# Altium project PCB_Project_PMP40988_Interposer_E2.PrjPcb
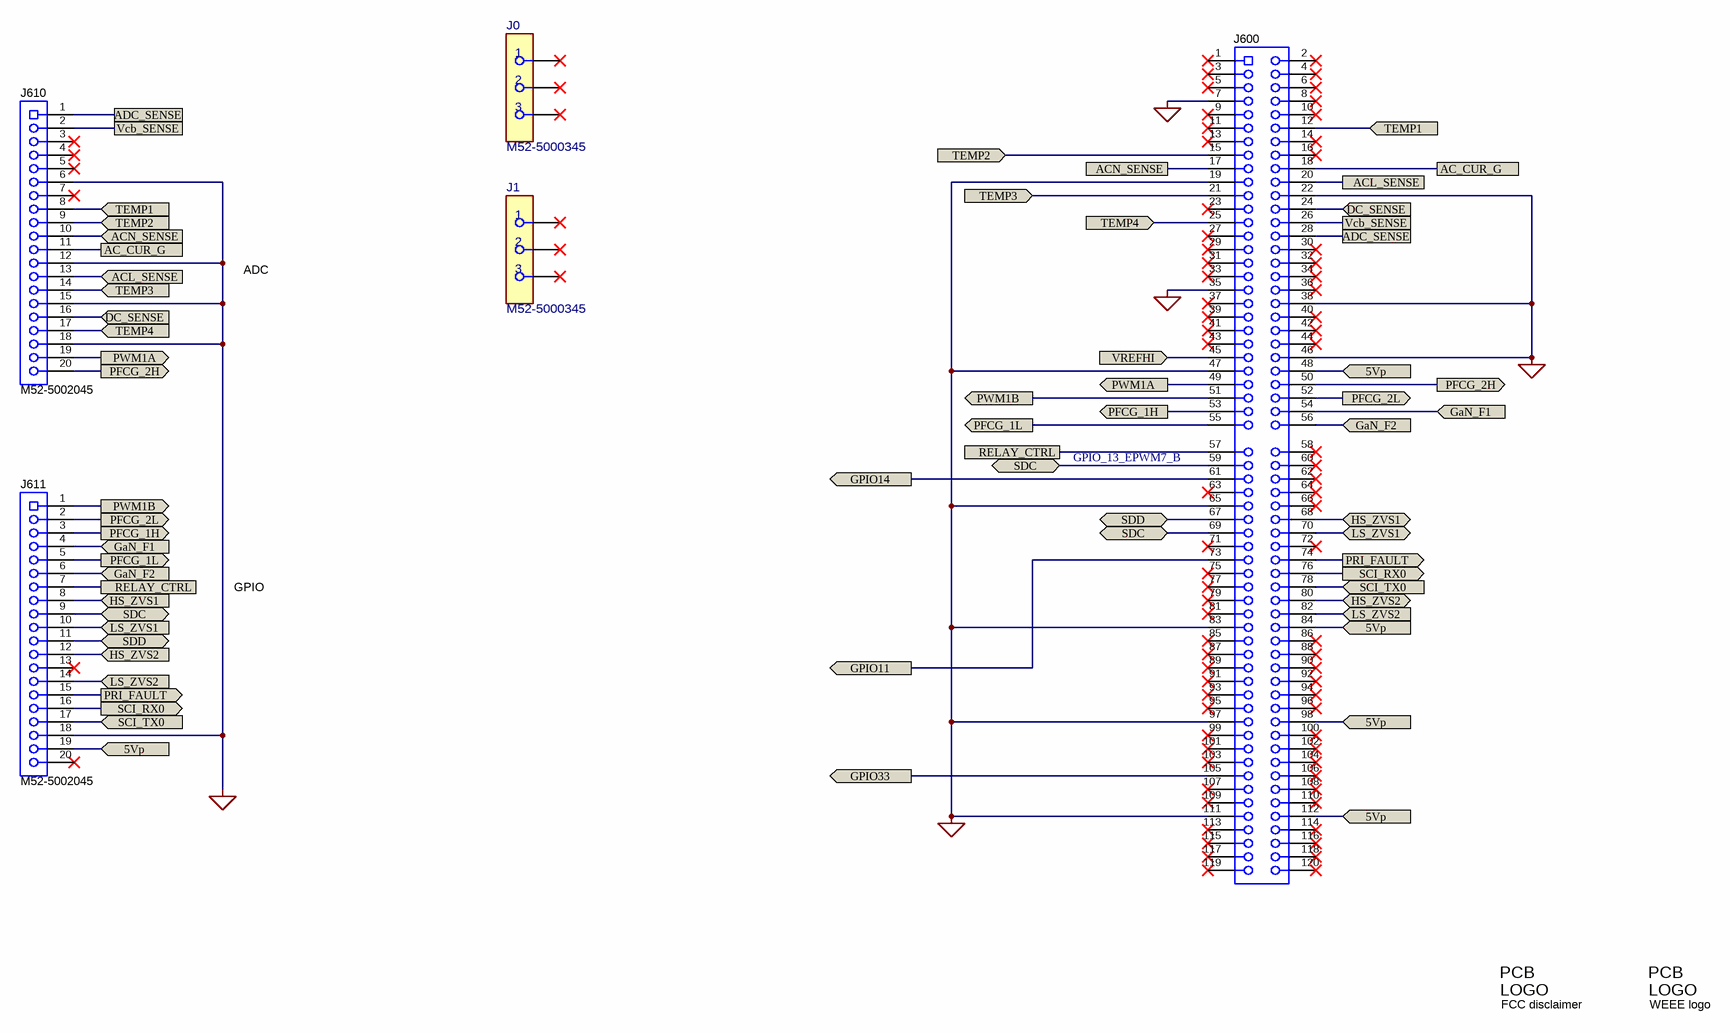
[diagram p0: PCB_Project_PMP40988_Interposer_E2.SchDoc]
CopyrightYear: 2022; PCB_Layout: Brent McDonald; PCB_Rev: E2; PRJ_Customer: Public Release; PRJ_Engineer: Brent McDonald; PRJ_Number: PMP40988_Interposer; PRJ_Title: Interposer for 280049C EVM; SCH_Rev: E2; TechSupport: http://www.ti.com/support; TID: N/A
1 sheet, 7 parts. Net scope: flat (ports and power ports of the same name join across sheets).
Board file: PCB_Project_PMP40988_Interposer_E2.PcbDoc

## Sheet PCB_Project_PMP40988_Interposer_E2.SchDoc
size 431 x 279 mm; Date: Not shown in title block; ApprovedBy: Not shown in title block; CheckedBy: Not shown in title block; Author: Not shown in title block; CompanyName: Not shown in title block; DrawnBy: San Chen; Engineer: Not shown in title block; Organization: Not shown in title block; Address1: Not shown in title block; Address2: Not shown in title block; Address3: Not shown in title block; Address4: Not shown in title block; DocumentNumber: 1; Revision: Use project parameter SCH_Rev; SheetNumber: 1; SheetTotal: 1; PageSetup: Record=PageOptions¦CenterHorizontal=True¦CenterVertical=True¦PrintScale=1.00¦XCorrection=1.00¦YCorrection=1.00¦PrintKind=0¦BorderSize=5000000¦LeftOffset=0¦BottomOffset=0¦Orientation=2¦PaperLength=1000¦PaperWidth=1000¦Scale=100¦PaperSource=15¦PrintQuality=600¦MediaType=1¦DitherType=10¦PaperKind=Letter¦PrintScaleMode=1

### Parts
J0  M52-5000345  [FP-M52-5000345_HDR3-MFG]
J1  M52-5000345  [FP-M52-5000345_HDR3-MFG]
J600  HSEC8-160-01-L-DV-A-BL  [controlCARD-120HSEC]  (value not drawn)
J610  M52-5002045  [M52-5002045]
J611  M52-5002045  [M52-5002045]
Logo605  FCC disclaimer  [FCC_disclaimer]  (no BOM)
Logo606  WEEE logo  [WEEE_Minimum]  (no BOM)

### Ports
5Vp (in), AC_CUR_G, ACL_SENSE, ACL_SENSE (in), ACN_SENSE, ACN_SENSE (in), ADC_SENSE, DC_SENSE (in), GaN_F1 (in), GaN_F2 (in), GPIO11 (out), GPIO14 (out), GPIO33 (out), HS_ZVS1 (bidir), HS_ZVS1 (in), HS_ZVS2 (bidir), HS_ZVS2 (in), LS_ZVS1 (bidir), LS_ZVS1 (in), LS_ZVS2 (in), PFCG_1H (out), PFCG_1L (out), PFCG_2H (out), PFCG_2L (out), PRI_FAULT (out), PWM1A (out), PWM1B (out), RELAY_CTRL, SCI_RX0 (out), SCI_TX0 (in), SDC (bidir), SDD (bidir), TEMP1 (in), TEMP2 (in), TEMP3 (in), TEMP4 (in), Vcb_SENSE, VREFHI (in)

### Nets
PGND: J600.7 J600.19 J600.22 J600.35 J600.38 J600.46 J600.47 J600.65 J600.83 J600.97 J600.111 J610.6 J610.12 J610.15 J610.18 J611.18
5Vp: J600.48 J600.84 J600.98 J600.112 J611.19 ; port 5Vp
AC_CUR_G: J600.18 J610.11 ; port AC_CUR_G
ACL_SENSE: J600.20 J610.13 ; port ACL_SENSE
ACN_SENSE: J600.17 J610.10 ; port ACN_SENSE
ADC_SENSE: J600.28 J610.1 ; port ADC_SENSE
DC_SENSE: J600.24 J610.16 ; port DC_SENSE
GaN_F1: J600.54 J611.4 ; port GaN_F1
GaN_F2: J600.56 J611.6 ; port GaN_F2
GPIO11: J600.73 ; port GPIO11
GPIO14: J600.61 ; port GPIO14
GPIO33: J600.105 ; port GPIO33
HS_ZVS1: J600.68 J611.8 ; port HS_ZVS1
HS_ZVS2: J600.80 J611.12 ; port HS_ZVS2
LS_ZVS1: J600.70 J611.10 ; port LS_ZVS1
LS_ZVS2: J600.82 J611.14 ; port LS_ZVS2
PFCG_1H: J600.53 J611.3 ; port PFCG_1H
PFCG_1L: J600.55 J611.5 ; port PFCG_1L
PFCG_2H: J600.50 J610.20 ; port PFCG_2H
PFCG_2L: J600.52 J611.2 ; port PFCG_2L
PRI_FAULT: J600.74 J611.15 ; port PRI_FAULT
PWM1A: J600.49 J610.19 ; port PWM1A
PWM1B: J600.51 J611.1 ; port PWM1B
RELAY_CTRL: J600.57 J611.7 ; port RELAY_CTRL
SCI_RX0: J600.76 J611.16 ; port SCI_RX0
SCI_TX0: J600.78 J611.17 ; port SCI_TX0
SDC: J600.59 J600.69 J611.9 ; port SDC
SDD: J600.67 J611.11 ; port SDD
TEMP1: J600.12 J610.8 ; port TEMP1
TEMP2: J600.15 J610.9 ; port TEMP2
TEMP3: J600.21 J610.14 ; port TEMP3
TEMP4: J600.25 J610.17 ; port TEMP4
Vcb_SENSE: J600.26 J610.2 ; port Vcb_SENSE
VREFHI: J600.45 ; port VREFHI

Not connected (* = marked no-connect by the designer): J0 1* 2* 3*; J1 1* 2* 3*; J600 1* 2* 3* 4* 5* 6* 8* 9* 10* 11* 13* 14* 16* 23* 27* 29* 30* 31* 32* 33* 34* 36* 37* 39* 40* 41* 42* 43* 44* 58* 60* 62* 63* 64* 66* 71* 72* 75* 77* 79* 81* 85* 86* 87* 88* 89* 90* 91* 92* 93* 94* 95* 96* 99* 100* 101* 102* 103* 104* 106* 107* 108* 109* 110* 113* 114* 115* 116* 117* 118* 119* 120*; J610 3* 4* 5* 7*; J611 13* 20*

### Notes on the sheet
- ADC
- GPIO_13_EPWM7_B
- GPIO

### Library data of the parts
J0 J1 = CMP-0097095-1: 3 Position Receptacle Connector 0.050" (1.27mm) Through Hole Gold; Manufacturer: Harwin; Is Female: yes; Row_Count: 1; AEC Qualified: No; SizeZ_mm: 4.75mm; Conn Orientation: Vertical; Conn Gender: Female; ContactFinish: Gold,Nickel; Current_A: 1A
J600 = CMP-0003814-2: C2000 controlCARD-120HSEC connector, SMT; Manufacturer: Samtec; Note: The pin numbering does not match Samtec datasheet
J610 J611 = Receptacle_20x1: Receptacle, 20x1, 1.27mm, TH; Manufacturer: Harwin Inc.; CT: False; CompType: Socket
Logo605 = CMP-0074847-1: FCC_disclaimer; Library Reference: Logo
Logo606 = CMP-0074769-1

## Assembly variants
001: not fitted FID1 FID2 FID3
